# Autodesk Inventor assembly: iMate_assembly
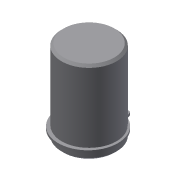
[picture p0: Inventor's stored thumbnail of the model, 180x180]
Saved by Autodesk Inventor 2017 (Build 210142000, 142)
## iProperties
Created: 2016-08
Part Number: iMate_assembly
Document SubType Name: Assembly
Designer: Sandeep
Author: Sandeep
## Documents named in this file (3)
- D:\KAVITA\Autodesk Inventor_2017_Project\Part's File\Inventor_2016_tut\c17_Inv_tut_2016\c17_tut02\iMate_assembly.iam
- D:\KAVITA\Autodesk Inventor_2017_Project\Part's File\Inventor_2016_tut\c17_Inv_tut_2016\c17_tut02\Shaft.ipt
- D:\KAVITA\Autodesk Inventor_2017_Project\Part's File\Inventor_2016_tut\c17_Inv_tut_2016\c17_tut02\circlip.ipt
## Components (2 placed, 2 different names)
1. Shaft:1
2. circlip:1
